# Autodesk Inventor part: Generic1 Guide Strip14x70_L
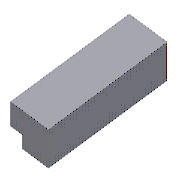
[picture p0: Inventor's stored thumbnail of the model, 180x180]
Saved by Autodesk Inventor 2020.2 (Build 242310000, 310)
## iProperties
Manager: www.cadconsulting.pl
Company: Fabian Stasiak CAD Consulting
Created: 2014-02
Part Number: Generic1 Guide Strip14x70_L
Material: DIN 1.2842
Description: Tor prowadnicy
Document SubType Name: Modeling
Designer: F.Stasiak
Standard Revision: 1
Manufacturer: Generic
Language: pl-PL
Size Designation: 14x70_L
Categories: <MemberInstance><Categories><Category DisplayName="Forma wtryskowa" InternalName="349578f2-f4d4-4954-8c09-8e99297a61c0" Mnemonic="MOLD"><Category DisplayName="K
Density: 7.66 g/cm^3
Appearance: Aluminum (Machined)
Catalog Web Link: www.expertbooks.pl
IsCustomPart: 1
Position: L
Part Type: 2
Author: F.Stasiak
Subject: Zbiór ćwiczeń. Autodesk Inventor 2020. Kurs Professional
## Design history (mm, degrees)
sketch "Sketch1"
  geometry: L1 (0, -6)-(0, 8) reference; L2 (-17.5, 6)-(-31.5, 6); L3 (-31.5, 6)-(-31.5, -4); L4 (-31.5, -4)-(-22.5, -4); L5 (-22.5, -4)-(-22.5, 0); L6 (-22.5, 0)-(-17.5, 0); L7 (-17.5, 0)-(-17.5, 6); 1 further point
  constraints: 12 end point, 3 horizontal, 3 vertical, 1 horizontal alignment
  dimensions: "d235" = 14 distance of L2.start L2.end (derived); "d236" = 10 distance of L2.end L3.end (derived); "d237" = 5 distance of L5.end L6.end (derived); "d238" = 4 distance of L4.end L5.end (derived); "d239" = 17.5 distance between parallel lines of L7 L1 (derived)
extrude "Wyciągnięcie proste_L" new body sketch "Sketch1" distance "d27" = 70 (= GS_l1); taper "d28" = 0 deg
workplane "Work Plane1"
feature "Powierzchnia zszycia1" dims "d272" = 0.254 (derived)
sketch "Sketch4"
  geometry: L1 (17.5, 0)-(17.5, 6); L2 (17.5, 6)-(31.5, 6); L3 (31.5, 6)-(31.5, -4); L4 (31.5, -4)-(22.5, -4); L5 (22.5, -4)-(22.5, 0); L6 (17.5, 0)-(22.5, 0); L7 (0, 8)-(0, -6) reference; 1 further point
  constraints: 12 end point, 3 parallel, 1 horizontal, 1 horizontal alignment, 1 perpendicular, 1 vertical
  dimensions: "d101" = 10 distance between parallel lines of L4 L2 (= GS_h2); "d240" = 14 distance of L1.end L2.end (derived); "d241" = 4 distance of L4.end L5.end (derived); "d242" = 5 distance of L1.start L5.end (derived); "d243" = 17.5 distance between parallel lines of L1 L7 (derived)
extrude "Wyciągnięcie proste_R" new body sketch "Sketch4" distance "d107" = 70 (derived); taper "d108" = 0 deg
workplane "Work Plane2"
feature "Powierzchnia zszycia2" dims "d273" = 0.254 (derived)
body "Solid1"
sketch "Sketch2"
  geometry: L1 (0, 14)-(0, 0); L2 (170, 14)-(170, 0); L3 (70, 0)-(70, 14) reference; L4 (0, 14)-(70, 14) reference; L5 (0, 0)-(70, 0) reference; L6 (0, 14)-(170, 14); L7 (0, 0)-(170, 0); 3 further points
  constraints: 8 end point, 3 point on line, 2 horizontal, 2 midpoint, 2 vertical
  dimensions: "d255" = 100 distance between parallel lines of L3 L2 (derived)
body "Srf1"
body "Srf2"
body "Srf3"
body "Srf4"
sketch "Sketch5"
  geometry: L1 (0, 14)-(170, 14); L2 (170, 14)-(170, 0); L3 (170, 0)-(0, 0); L4 (0, 0)-(0, 14); L5 (0, 14)-(70, 14) reference; L6 (70, 0)-(70, 14) reference; L7 (0, 0)-(70, 0) reference; 2 further points
  constraints: 8 end point, 6 point on line, 2 parallel, 1 collinear, 1 horizontal, 1 midpoint, 1 perpendicular
  dimensions: "d136" = 100 distance between parallel lines of L2 L6 (derived)
body "Srf5"
body "Srf6"
body "Srf7"
body "Srf8"
feature "WyciągnięcieProstePow1" dims "d81" = 10.5 (derived), "d82" = 0
feature "Zamknięcie obwiedni1" dims "d84" = 0, "d256" = 0, "d257" = 0, "d258" = 0, "d259" = 0
feature "Zamknięcie obwiedni2" dims "d86" = 0, "d260" = 0, "d261" = 0, "d262" = 0, "d263" = 0
feature "WyciągnięcieProstePow3" dims "d138" = 10.5 (derived), "d139" = 0
feature "Zamknięcie obwiedni5" dims "d250" = 0, "d264" = 0, "d265" = 0, "d266" = 0, "d267" = 0
feature "Zamknięcie obwiedni6" dims "d252" = 0, "d268" = 0, "d269" = 0, "d270" = 0, "d271" = 0
other parameters: "GS_b" = 14 [user parameter], "GS_l1" = 70 [user parameter; used in 1 equation term], "GS_h2" = 10 [user parameter; used in 1 equation term], "GS_t1" = 5 [user parameter], "GS_h3" = 4 [user parameter], "GS_es1" = 0.5 [user parameter; used in 1 equation term], "GS_esr" = 2.5 [user parameter], "GS_esw" = 5 [user parameter], "GS_esl1" = 0 [user parameter], "d96" = 0.5 (= GS_es1), "d134" = 0.5 (derived), "SL_b1" = 35 [user parameter]
